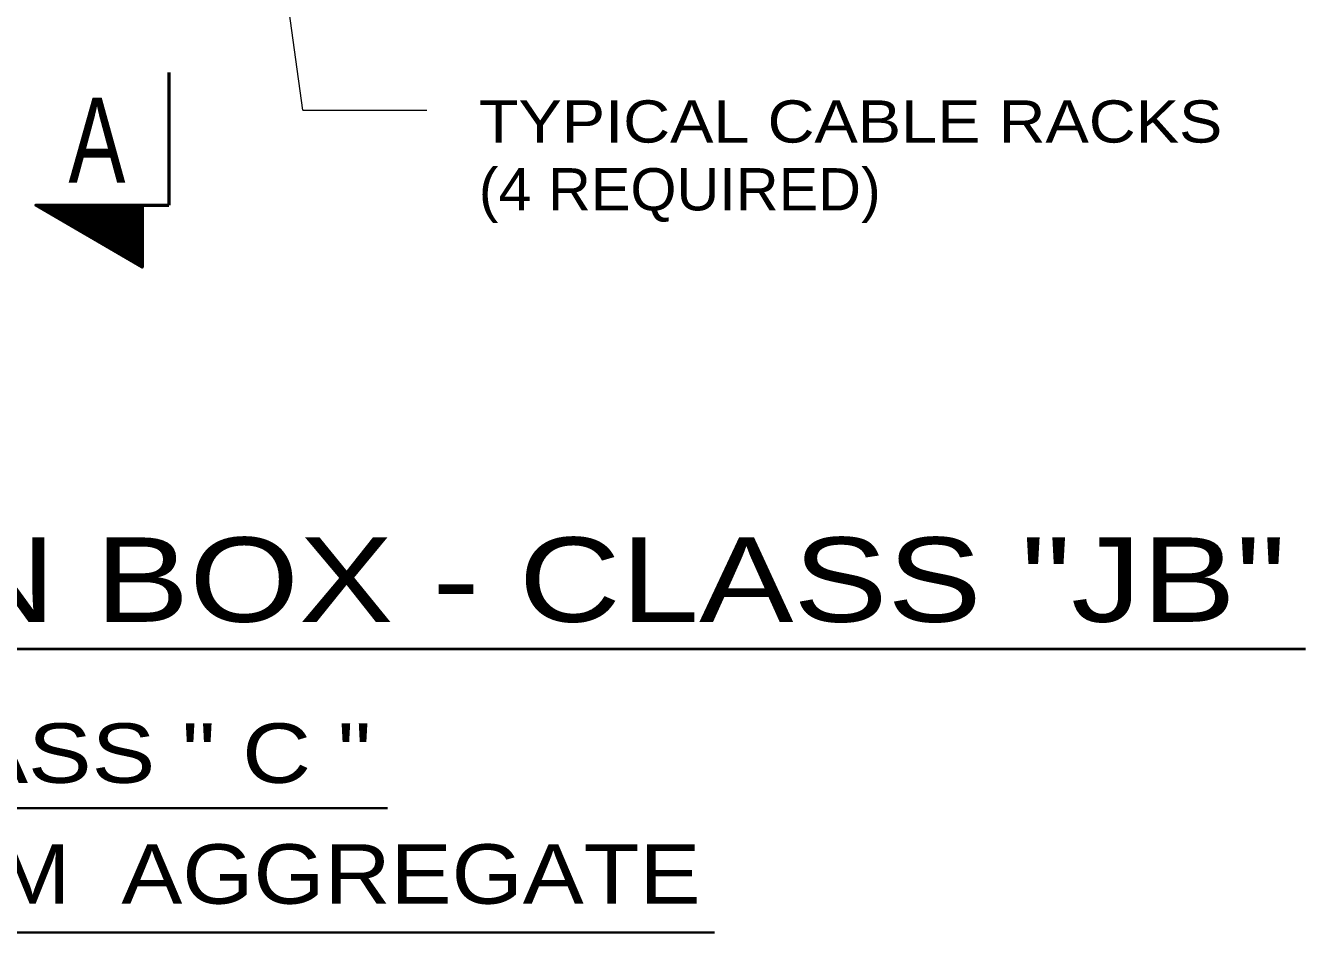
# Model space of a CAD drawing. Extents: x 312583 to 312854, y 144419 to 144597.
# Drawn here: x 312650.21 to 312673.24, y 144526.37 to 144542.68 of the extents above; entities that cross this region are included whole.
import ezdxf
from ezdxf.enums import TextEntityAlignment as Align

# ---------------------------------------------------------------- set-up
doc = ezdxf.new("R2010")
doc.units = 0
doc.header["$LTSCALE"] = 0.3
doc.layers.add('1', color=7, linetype='Continuous', lineweight=40)
doc.layers.add('2', color=7, linetype='Continuous', lineweight=13)

msp = doc.modelspace()

# ---------------------------------------------------------------- linework, layer by layer
at = {"layer": '1', "lineweight": 53}
for p in [(312652.7891, 144541.8421), (312652.3138, 144539.4501)]:
    msp.add_line(p, (312652.7891, 144539.4501), dxfattribs=at)
at = {"layer": '1', "lineweight": 35}
for p, q in [((312650.4124, 144539.4501), (312650.4124, 144539.4348)), ((312650.4431, 144539.4501), (312650.4354, 144539.4271)), ((312650.4738, 144539.4501), (312650.4508, 144539.4118)), ((312650.4968, 144539.4501), (312650.4738, 144539.4041)), ((312650.5274, 144539.4501), (312650.4968, 144539.3888)), ((312650.5504, 144539.4501), (312650.5121, 144539.3811)), ((312650.5811, 144539.4501), (312650.5351, 144539.3658)), ((312650.6118, 144539.4501), (312650.5581, 144539.3581)), ((312650.6424, 144539.4501), (312650.5734, 144539.3428)), ((312650.6654, 144539.4501), (312650.5964, 144539.3351)), ((312650.6884, 144539.4501), (312650.6194, 144539.3198)), ((312650.7191, 144539.4501), (312650.6424, 144539.3121)), ((312650.7421, 144539.4501), (312650.6578, 144539.2968)), ((312650.7728, 144539.4501), (312650.6808, 144539.2814)), ((312650.8034, 144539.4501), (312650.7038, 144539.2738)), ((312650.8341, 144539.4501), (312650.7191, 144539.2584)), ((312650.8571, 144539.4501), (312650.7421, 144539.2431)), ((312650.8878, 144539.4501), (312650.7651, 144539.2354)), ((312650.9108, 144539.4501), (312650.7804, 144539.2201)), ((312650.9414, 144539.4501), (312650.8034, 144539.2124)), ((312650.9721, 144539.4501), (312650.8264, 144539.1971)), ((312650.9951, 144539.4501), (312650.8418, 144539.1894)), ((312651.0258, 144539.4501), (312650.8724, 144539.1741)), ((312651.0488, 144539.4501), (312650.8878, 144539.1664)), ((312651.0794, 144539.4501), (312650.9108, 144539.1511)), ((312651.1101, 144539.4501), (312650.9338, 144539.1434)), ((312651.1331, 144539.4501), (312650.9491, 144539.1281)), ((312651.1638, 144539.4501), (312650.9721, 144539.1204)), ((312651.1868, 144539.4501), (312650.9951, 144539.1051)), ((312651.2174, 144539.4501), (312651.0104, 144539.0898)), ((312651.2404, 144539.4501), (312651.0334, 144539.0821)), ((312651.2711, 144539.4501), (312651.0564, 144539.0668)), ((312651.3018, 144539.4501), (312651.0718, 144539.0514)), ((312651.3324, 144539.4501), (312651.0948, 144539.0438)), ((312651.3554, 144539.4501), (312651.1178, 144539.0284)), ((312651.3784, 144539.4501), (312651.1408, 144539.0208)), ((312651.4091, 144539.4501), (312651.1561, 144539.0054)), ((312651.4398, 144539.4501), (312651.1791, 144538.9978)), ((312651.4628, 144539.4501), (312651.2021, 144538.9824)), ((312651.4934, 144539.4501), (312651.2174, 144538.9748)), ((312651.5241, 144539.4501), (312651.2404, 144538.9594)), ((312651.5471, 144539.4501), (312651.2634, 144538.9518)), ((312651.5778, 144539.4501), (312651.2788, 144538.9364)), ((312651.6084, 144539.4501), (312651.3018, 144538.9288)), ((312651.6314, 144539.4501), (312651.3248, 144538.9134)), ((312651.6621, 144539.4424), (312651.3401, 144538.8981)), ((312651.6851, 144539.4501), (312651.3708, 144538.8904)), ((312651.7158, 144539.4501), (312651.3861, 144538.8751)), ((312651.7388, 144539.4501), (312651.4091, 144538.8674)), ((312651.7694, 144539.4501), (312651.4321, 144538.8521)), ((312651.8001, 144539.4501), (312651.4474, 144538.8444)), ((312651.8308, 144539.4501), (312651.4704, 144538.8291)), ((312651.8538, 144539.4501), (312651.4934, 144538.8214)), ((312651.8768, 144539.4501), (312651.5088, 144538.8061)), ((312651.9074, 144539.4424), (312651.5318, 144538.7984)), ((312651.9381, 144539.4501), (312651.5548, 144538.7831)), ((312651.9611, 144539.4501), (312651.5701, 144538.7754)), ((312651.9918, 144539.4501), (312651.5931, 144538.7601)), ((312652.0224, 144539.4501), (312651.6161, 144538.7448)), ((312652.0454, 144539.4501), (312651.6391, 144538.7371)), ((312652.0761, 144539.4501), (312651.6544, 144538.7218)), ((312652.1068, 144539.4501), (312651.6774, 144538.7064)), ((312652.1298, 144539.4424), (312651.7004, 144538.6988)), ((312652.1604, 144539.4424), (312651.7158, 144538.6834)), ((312652.1834, 144539.4501), (312651.7388, 144538.6758)), ((312652.2141, 144539.4501), (312651.7618, 144538.6604)), ((312652.2371, 144539.4501), (312651.7771, 144538.6528)), ((312652.2678, 144539.4501), (312651.8001, 144538.6374)), ((312652.2984, 144539.4501), (312651.8231, 144538.6298)), ((312652.3138, 144539.4271), (312651.8384, 144538.6144)), ((312652.3138, 144539.3734), (312651.8691, 144538.6068)), ((312652.3138, 144539.3351), (312651.8844, 144538.5914)), ((312652.3138, 144539.2814), (312651.9074, 144538.5838)), ((312652.3138, 144539.2354), (312651.9304, 144538.5684)), ((312652.3138, 144539.1894), (312651.9458, 144538.5531)), ((312652.3138, 144539.1434), (312651.9688, 144538.5454)), ((312652.3138, 144539.0898), (312651.9918, 144538.5301)), ((312652.3138, 144539.0438), (312652.0071, 144538.5148)), ((312652.3138, 144538.9978), (312652.0301, 144538.5071)), ((312652.3138, 144538.9441), (312652.0454, 144538.4918)), ((312652.3138, 144538.8981), (312652.0684, 144538.4841)), ((312652.3138, 144538.8521), (312652.0914, 144538.4688)), ((312652.3138, 144538.7984), (312652.1068, 144538.4611)), ((312652.3138, 144538.7524), (312652.1374, 144538.4458)), ((312652.3138, 144538.7064), (312652.1528, 144538.4381)), ((312652.3138, 144538.6604), (312652.1758, 144538.4228)), ((312652.3138, 144538.6068), (312652.1988, 144538.4151)), ((312652.3138, 144538.5684), (312652.2141, 144538.3998)), ((312652.3138, 144538.5148), (312652.2371, 144538.3921)), ((312652.3138, 144538.4688), (312652.2601, 144538.3768)), ((312652.3138, 144538.4151), (312652.2754, 144538.3614)), ((312652.3138, 144538.3691), (312652.2984, 144538.3538))]:
    msp.add_line(p, q, dxfattribs=at)
at = {"layer": '1', "lineweight": 53}
msp.add_lwpolyline([(312652.3138, 144539.4501), (312652.3138, 144538.3384), (312650.3971, 144539.4501)], close=True, dxfattribs=at)
at = {"layer": '2'}
msp.add_line((312655.2041, 144541.1598), (312657.4351, 144541.1598), dxfattribs=at)
at = {"layer": '2', "lineweight": 40}
msp.add_line((312618.0343, 144531.4691), (312673.2441, 144531.4691), dxfattribs=at)
at = {"layer": '2', "lineweight": 35}
for p, q in [((312636.6692, 144528.5996), (312656.7254, 144528.5996)), ((312629.8656, 144526.3655), (312662.613, 144526.3655))]:
    msp.add_line(p, q, dxfattribs=at)
at = {"layer": '2'}
msp.add_lwpolyline([(312655.2041, 144541.1598), (312654.0311, 144549.6391), (312656.4844, 144551.1111)], dxfattribs=at)

# ---------------------------------------------------------------- texts
at = {"layer": '1', "width": 0.75}
msp.add_text('A', height=1.533, dxfattribs=at).set_placement((312651.4973, 144539.8564), align=Align.CENTER)
at = {"layer": '1'}
for s, width, p in [('TYPICAL CABLE RACKS', 1.15, (312658.3691, 144540.578)), ('(4 REQUIRED)', 1.05, (312658.3691, 144539.358))]:
    msp.add_text(s, height=0.76, dxfattribs=dict(at, width=width)).set_placement(p)
at = {"layer": '2'}
for s, height, width, p in [('450 BY 900 MM JUNCTION BOX - CLASS "JB"', 1.52, 1.25, (312645.9415, 144531.954)), ('CONCRETE CLASS " C "', 1.07, 1.2, (312646.6205, 144529.0568)), ('USING APPROVED  16 MM  AGGREGATE', 1.07, 1.15, (312646.3134, 144526.8814))]:
    msp.add_text(s, height=height, dxfattribs=dict(at, width=width)).set_placement(p, align=Align.CENTER)

doc.saveas('drawing.dxf')
